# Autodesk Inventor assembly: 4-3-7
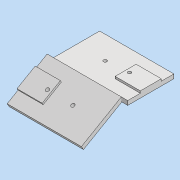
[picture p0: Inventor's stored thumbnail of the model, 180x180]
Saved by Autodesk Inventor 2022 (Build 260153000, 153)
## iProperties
Created: 2021-07
Part Number: 4-3-7
Document SubType Name: Assembly
Designer: DesignLab
Author: DesignLab
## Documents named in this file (2)
- d:\Users\DesignLab\Desktop\ver2022\ch04\4-3-7.iam
- d:\Users\DesignLab\Desktop\ver2022\ch04\03-ベース板_完成.ipt
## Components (2 placed, 1 different names)
1. 03-ベース板_完成:1 — メイト:1, 角度:1
2. 03-ベース板_完成:2 — メイト:1, 角度:1
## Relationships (2: Mate 1, Angle 1)
- メイト:1 [Mate]: 03-ベース板_完成:1 ↔ 03-ベース板_完成:2
- 角度:1 [Angle]: 03-ベース板_完成:1 ↔ 03-ベース板_完成:2
